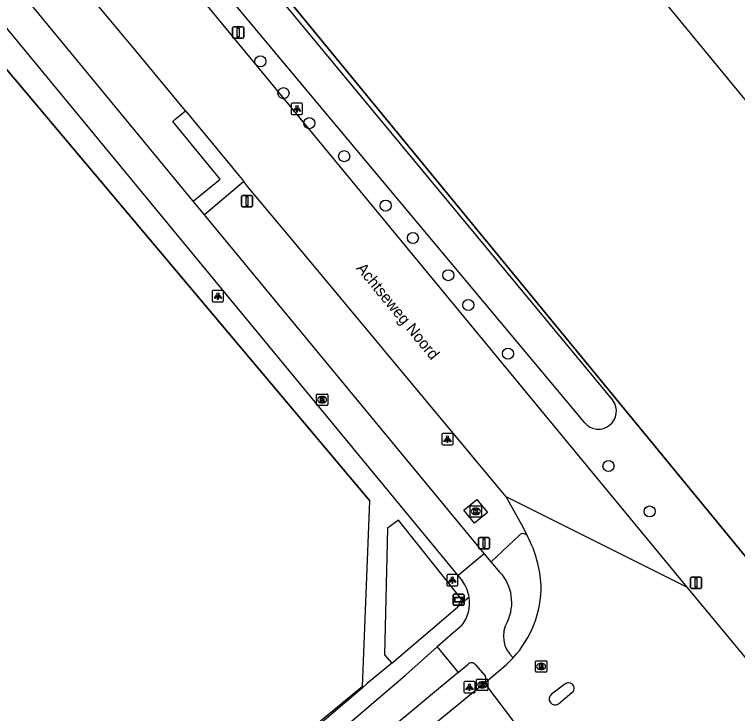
# Model space of a CAD drawing. Extents: x 156141 to 158132, y 385651 to 388399.
# Drawn here: x 157411.4 to 157475.3, y 386650.1 to 386711.9 of the extents above; entities that cross this region are included whole.
import ezdxf

# ---------------------------------------------------------------- set-up
doc = ezdxf.new("R2010")
doc.units = 0
for name, color, linetype in [('IMGEO_Berm_groen', 7, 'Continuous'), ('IMGEO_Berm_open', 7, 'Continuous'), ('IMGEO_Boom', 7, 'Continuous'), ('IMGEO_Fietspad_gesloten', 7, 'Continuous'), ('IMGEO_Fietspad_open', 7, 'Continuous'), ('IMGEO_Groenvoorziening', 7, 'Continuous'), ('IMGEO_Hek', 7, 'Continuous'), ('IMGEO_Kolk', 7, 'Continuous'), ('IMGEO_Lichtpunt', 7, 'Continuous'), ('IMGEO_Openbare_ruimte_label', 7, 'Continuous'), ('IMGEO_Rijbaan_lokaal_gesloten', 7, 'Continuous'), ('IMGEO_Rijbaan_lokaal_open', 7, 'Continuous'), ('IMGEO_Rioolput', 7, 'Continuous'), ('IMGEO_Verkeersbordpaal', 7, 'Continuous'), ('IMGEO_Verklikker', 7, 'Continuous'), ('IMGEO_Voetpad_open', 7, 'Continuous'), ('IMGEO_Waterloop', 7, 'Continuous')]:
    doc.layers.add(name, color=color, linetype=linetype)

msp = doc.modelspace()

# ---------------------------------------------------------------- linework, layer by layer
at = {"layer": 'IMGEO_Berm_groen'}
for points in [[(157442.134, 386652.366), (157442.138, 386652.478), (157442.779, 386668.903), (157366.554, 386759.475), (157367.449, 386760.214), (157328.468, 386807.48), (157305.149, 386835.748), (157305.371, 386835.926), (157306.254, 386836.693)], [(157453.195, 386667.87), (157452.049, 386666.904), (157451.094, 386668.062), (157452.249, 386668.999), (157453.195, 386667.87)], [(157450.547, 386659.488), (157450.88, 386660.201), (157445.328, 386667.193), (157444.342, 386666.47), (157444.073, 386655.269), (157444.717, 386654.548)]]:
    msp.add_lwpolyline(points, dxfattribs=at)
at = {"layer": 'IMGEO_Berm_open'}
msp.add_lwpolyline([(157456.011, 386665.871), (157453.509, 386663.504)], dxfattribs=at)
msp.add_arc((157456.324, 386665.519), 0.471, 25.37119, 131.65084, dxfattribs=at)
at = {"layer": 'IMGEO_Boom'}
for centre in [(157433.117, 386707.739), (157435.158, 386704.93), (157437.436, 386702.279), (157440.518, 386699.359), (157444.183, 386694.993), (157446.592, 386692.131), (157449.727, 386688.836), (157451.485, 386686.203), (157454.999, 386681.904), (157463.879, 386671.978), (157467.514, 386667.952)]:
    msp.add_circle(centre, 0.489, dxfattribs=at)
at = {"layer": 'IMGEO_Fietspad_gesloten'}
for points in [[(157306.254, 386836.693), (157307.173, 386835.584), (157317.744, 386823.128), (157324.427, 386815.039), (157329.795, 386808.571), (157345.284, 386789.91), (157378.223, 386750), (157413.308, 386707.49), (157450.572, 386662.298)], [(157427.18, 386695.379), (157410.042, 386716.143)], [(157428.171, 386694.179), (157427.18, 386695.379)], [(157452.881, 386664.24), (157428.171, 386694.179)], [(157450.572, 386662.298), (157452.881, 386664.24)], [(157388.924, 386606.194), (157432.202, 386641.872), (157439.098, 386647.651), (157445.938, 386653.466), (157448.75, 386655.977)], [(157448.75, 386655.977), (157450.605, 386653.724)], [(157450.605, 386653.724), (157437.983, 386643.221), (157390.577, 386604.195)]]:
    msp.add_lwpolyline(points, dxfattribs=at)
at = {"layer": 'IMGEO_Fietspad_open'}
for points in [[(157453.509, 386663.504), (157452.881, 386664.24)], [(157454.305, 386662.57), (157453.509, 386663.504)], [(157450.572, 386662.298), (157450.979, 386661.776)], [(157450.909, 386657.873), (157450.08, 386657.165), (157448.75, 386655.977)], [(157450.605, 386653.724), (157451.438, 386654.417)], [(157452.12, 386654.393), (157452.973, 386653.414)]]:
    msp.add_lwpolyline(points, dxfattribs=at)
for centre, radius, start, end in [((157451.386, 386659.914), 3.946, 334.70293, 42.29924), ((157448.401, 386659.871), 3.206, 8.88283, 36.46074), ((157448.398, 386659.87), 3.209, 321.49988, 8.88633), ((157457.115, 386656.932), 2.52, 149.05739, 229.14689), ((157451.77, 386654.14), 0.432, 35.79806, 140.17105), ((157452.519, 386653.134), 0.534, 319.38165, 31.69536)]:
    msp.add_arc(centre, radius, start, end, dxfattribs=at)
at = {"layer": 'IMGEO_Groenvoorziening'}
msp.add_lwpolyline([(157429.239, 386720.934), (157498.496, 386636.57), (157500, 386634.738), (157500.222, 386634.47), (157521.784, 386608.449), (157576.014, 386543.004), (157577.215, 386541.551)], dxfattribs=at)
at = {"layer": 'IMGEO_Hek'}
for points in [[(157367.449, 386760.214), (157366.554, 386759.475), (157442.779, 386668.903)], [(157498.496, 386636.57), (157429.239, 386720.934)], [(157442.138, 386652.478), (157442.779, 386668.903)], [(157442.138, 386652.478), (157400.211, 386617.877), (157400.156, 386617.832)], [(157442.134, 386652.366), (157442.138, 386652.478)]]:
    msp.add_lwpolyline(points, dxfattribs=at)
at = {"layer": 'IMGEO_Kolk'}
for p, q in [((157451.655, 386667.535), (157451.655, 386668.387)), ((157451.73, 386668.461), (157452.582, 386668.461)), ((157452.143, 386668.241), (157452.168, 386668.241)), ((157452.656, 386668.387), (157452.656, 386667.535)), ((157452.582, 386667.461), (157451.73, 386667.461)), ((157452.166, 386667.681), (157452.141, 386667.681)), ((157452.225, 386652.206), (157452.225, 386653.058)), ((157452.3, 386653.132), (157453.152, 386653.132)), ((157452.713, 386652.912), (157452.738, 386652.912)), ((157453.226, 386653.058), (157453.226, 386652.206)), ((157453.152, 386652.132), (157452.3, 386652.132)), ((157452.736, 386652.352), (157452.711, 386652.352))]:
    msp.add_line(p, q, dxfattribs=at)
for points in [[(157451.655, 386667.535), (157451.655, 386668.387)], [(157451.73, 386668.461), (157452.582, 386668.461)], [(157451.976, 386668.161), (157452.099, 386668.161), (157452.099, 386668.01), (157452.229, 386668.161), (157452.393, 386668.161), (157452.247, 386668.01), (157452.4, 386667.761), (157452.248, 386667.761), (157452.163, 386667.925), (157452.099, 386667.858), (157452.099, 386667.761), (157451.976, 386667.761), (157451.976, 386668.161)], [(157452.656, 386668.387), (157452.656, 386667.535)], [(157452.582, 386667.461), (157451.73, 386667.461)], [(157452.225, 386652.206), (157452.225, 386653.058)], [(157452.3, 386653.132), (157453.152, 386653.132)], [(157452.546, 386652.832), (157452.669, 386652.832), (157452.669, 386652.681), (157452.799, 386652.832), (157452.963, 386652.832), (157452.817, 386652.681), (157452.97, 386652.432), (157452.818, 386652.432), (157452.733, 386652.596), (157452.669, 386652.529), (157452.669, 386652.432), (157452.546, 386652.432), (157452.546, 386652.832)], [(157453.226, 386653.058), (157453.226, 386652.206)], [(157453.152, 386652.132), (157452.3, 386652.132)]]:
    msp.add_lwpolyline(points, dxfattribs=at)
for centre, start, end in [((157451.732, 386668.385), 91.55205, 178.44795), ((157451.732, 386668.385), 91.55205, 178.44795), ((157452.58, 386668.385), 1.55205, 88.44795), ((157452.58, 386668.385), 1.55205, 88.44795), ((157451.732, 386667.537), 181.55205, 268.44795), ((157451.732, 386667.537), 181.55205, 268.44795), ((157452.58, 386667.537), 271.55205, 358.44795), ((157452.58, 386667.537), 271.55205, 358.44795), ((157452.302, 386653.056), 91.55205, 178.44795), ((157452.302, 386653.056), 91.55205, 178.44795), ((157453.15, 386653.056), 1.55205, 88.44795), ((157453.15, 386653.056), 1.55205, 88.44795), ((157452.302, 386652.208), 181.55205, 268.44795), ((157452.302, 386652.208), 181.55205, 268.44795), ((157453.15, 386652.208), 271.55205, 358.44795), ((157453.15, 386652.208), 271.55205, 358.44795)]:
    msp.add_arc(centre, 0.0765, start, end, dxfattribs=at)
for centre, major_axis, ratio, start_param, end_param in [((157452.142, 386667.961), (-0.387, 0.002), 0.722429, 4.712389, 7.853982), ((157452.167, 386667.961), (-0.39, 0.002), 0.717154, 1.570796, 4.712389), ((157452.712, 386652.632), (-0.387, 0.002), 0.722429, 4.712389, 7.853982), ((157452.737, 386652.632), (-0.39, 0.002), 0.717154, 1.570796, 4.712389)]:
    msp.add_ellipse(centre, major_axis=major_axis, ratio=ratio, start_param=start_param, end_param=end_param, dxfattribs=at)
at = {"layer": 'IMGEO_Lichtpunt'}
for p, q in [((157435.846, 386703.949), (157435.846, 386703.142)), ((157435.846, 386703.949), (157435.846, 386703.142)), ((157436.748, 386704.044), (157435.94, 386704.044)), ((157436.748, 386704.044), (157435.94, 386704.044)), ((157436.842, 386703.142), (157436.842, 386703.949)), ((157436.842, 386703.142), (157436.842, 386703.949)), ((157435.94, 386703.048), (157436.748, 386703.048)), ((157435.94, 386703.048), (157436.748, 386703.048)), ((157428.86, 386687.396), (157428.86, 386686.589)), ((157428.86, 386687.396), (157428.86, 386686.589)), ((157429.762, 386687.491), (157428.954, 386687.491)), ((157429.762, 386687.491), (157428.954, 386687.491)), ((157429.856, 386686.589), (157429.856, 386687.396)), ((157429.856, 386686.589), (157429.856, 386687.396)), ((157428.954, 386686.495), (157429.762, 386686.495)), ((157428.954, 386686.495), (157429.762, 386686.495)), ((157449.149, 386674.745), (157449.149, 386673.938)), ((157449.149, 386674.745), (157449.149, 386673.938)), ((157450.051, 386674.84), (157449.243, 386674.84)), ((157450.051, 386674.84), (157449.243, 386674.84)), ((157450.145, 386673.938), (157450.145, 386674.745)), ((157450.145, 386673.938), (157450.145, 386674.745)), ((157449.243, 386673.844), (157450.051, 386673.844)), ((157449.243, 386673.844), (157450.051, 386673.844)), ((157449.58, 386662.29), (157449.58, 386661.483)), ((157449.58, 386662.29), (157449.58, 386661.483)), ((157450.482, 386662.385), (157449.674, 386662.385)), ((157450.482, 386662.385), (157449.674, 386662.385)), ((157450.576, 386661.483), (157450.576, 386662.29)), ((157450.576, 386661.483), (157450.576, 386662.29)), ((157449.674, 386661.389), (157450.482, 386661.389)), ((157449.674, 386661.389), (157450.482, 386661.389)), ((157451.095, 386652.822), (157451.095, 386652.015)), ((157451.095, 386652.822), (157451.095, 386652.015)), ((157451.997, 386652.917), (157451.189, 386652.917)), ((157451.997, 386652.917), (157451.189, 386652.917)), ((157452.091, 386652.015), (157452.091, 386652.822)), ((157452.091, 386652.015), (157452.091, 386652.822)), ((157451.189, 386651.921), (157451.997, 386651.921)), ((157451.189, 386651.921), (157451.997, 386651.921))]:
    msp.add_line(p, q, dxfattribs=at)
for points in [[(157436.22, 386703.613), (157436.259, 386703.585), (157436.071, 386703.323), (157436.033, 386703.35), (157436.22, 386703.613)], [(157436.322, 386703.565), (157436.369, 386703.565), (157436.369, 386703.243), (157436.322, 386703.243), (157436.322, 386703.565)], [(157436.432, 386703.585), (157436.47, 386703.612), (157436.657, 386703.35), (157436.618, 386703.322), (157436.432, 386703.585)], [(157429.234, 386687.06), (157429.273, 386687.032), (157429.085, 386686.77), (157429.047, 386686.797), (157429.234, 386687.06)], [(157429.336, 386687.012), (157429.383, 386687.012), (157429.383, 386686.69), (157429.336, 386686.69), (157429.336, 386687.012)], [(157429.446, 386687.032), (157429.484, 386687.059), (157429.671, 386686.797), (157429.632, 386686.769), (157429.446, 386687.032)], [(157449.523, 386674.409), (157449.562, 386674.381), (157449.374, 386674.119), (157449.336, 386674.146), (157449.523, 386674.409)], [(157449.625, 386674.361), (157449.672, 386674.361), (157449.672, 386674.039), (157449.625, 386674.039), (157449.625, 386674.361)], [(157449.735, 386674.381), (157449.773, 386674.408), (157449.96, 386674.146), (157449.921, 386674.118), (157449.735, 386674.381)], [(157449.954, 386661.954), (157449.993, 386661.926), (157449.805, 386661.664), (157449.767, 386661.691), (157449.954, 386661.954)], [(157450.056, 386661.906), (157450.103, 386661.906), (157450.103, 386661.584), (157450.056, 386661.584), (157450.056, 386661.906)], [(157450.166, 386661.926), (157450.204, 386661.953), (157450.391, 386661.691), (157450.352, 386661.663), (157450.166, 386661.926)], [(157451.469, 386652.486), (157451.508, 386652.458), (157451.32, 386652.196), (157451.282, 386652.223), (157451.469, 386652.486)], [(157451.571, 386652.438), (157451.618, 386652.438), (157451.618, 386652.116), (157451.571, 386652.116), (157451.571, 386652.438)], [(157451.681, 386652.458), (157451.719, 386652.485), (157451.906, 386652.223), (157451.867, 386652.195), (157451.681, 386652.458)]]:
    msp.add_lwpolyline(points, dxfattribs=at)
for centre in [(157436.345, 386703.747), (157429.359, 386687.194), (157449.648, 386674.543), (157450.079, 386662.088), (157451.594, 386652.62)]:
    msp.add_circle(centre, 0.0994, dxfattribs=at)
for centre, start, end in [((157435.94, 386703.949), 90, 180), ((157435.94, 386703.949), 90, 180), ((157436.748, 386703.949), 0, 90), ((157436.748, 386703.949), 0, 90), ((157435.94, 386703.142), 180, 270), ((157435.94, 386703.142), 180, 270), ((157436.748, 386703.142), 270, 0), ((157436.748, 386703.142), 270, 360), ((157428.954, 386687.396), 90, 180), ((157428.954, 386687.396), 90, 180), ((157429.762, 386687.396), 0, 90), ((157429.762, 386687.396), 0, 90), ((157428.954, 386686.589), 180, 270), ((157428.954, 386686.589), 180, 270), ((157429.762, 386686.589), 270, 0), ((157429.762, 386686.589), 270, 360), ((157449.243, 386674.745), 90, 180), ((157449.243, 386674.745), 90, 180), ((157450.051, 386674.745), 0, 90), ((157450.051, 386674.745), 0, 90), ((157449.243, 386673.938), 180, 270), ((157449.243, 386673.938), 180, 270), ((157450.051, 386673.938), 270, 0), ((157450.051, 386673.938), 270, 360), ((157449.674, 386662.29), 90, 180), ((157449.674, 386662.29), 90, 180), ((157450.482, 386662.29), 0, 90), ((157450.482, 386662.29), 0, 90), ((157449.674, 386661.483), 180, 270), ((157449.674, 386661.483), 180, 270), ((157450.482, 386661.483), 270, 0), ((157450.482, 386661.483), 270, 360), ((157451.189, 386652.822), 90, 180), ((157451.189, 386652.822), 90, 180), ((157451.997, 386652.822), 0, 90), ((157451.997, 386652.822), 0, 90), ((157451.189, 386652.015), 180, 270), ((157451.189, 386652.015), 180, 270), ((157451.997, 386652.015), 270, 0), ((157451.997, 386652.015), 270, 360)]:
    msp.add_arc(centre, 0.0946, start, end, dxfattribs=at)
at = {"layer": 'IMGEO_Rijbaan_lokaal_gesloten'}
for points in [[(157426.489, 386703.354), (157422.539, 386708.146), (157422.419, 386708.292), (157417.313, 386714.46), (157412.339, 386720.535)], [(157428.271, 386712.826), (157470.805, 386661.255)], [(157426.489, 386703.354), (157431.636, 386697.108)], [(157454.834, 386669.244), (157436.573, 386691.201), (157432.018, 386696.645), (157431.636, 386697.108)], [(157456.749, 386665.721), (157456.378, 386666.515), (157454.834, 386669.244)], [(157470.805, 386661.255), (157454.834, 386669.244)], [(157470.805, 386661.255), (157479.667, 386650.565), (157483.034, 386646.48)], [(157452.924, 386652.786), (157454.876, 386654.437), (157455.467, 386655.026)], [(157452.924, 386652.786), (157429.506, 386633.553), (157391.761, 386602.481)], [(157452.924, 386652.786), (157455.672, 386649.151)], [(157460.034, 386652.674), (157458.834, 386651.795)], [(157459.472, 386650.948), (157460.653, 386651.949)]]:
    msp.add_lwpolyline(points, dxfattribs=at)
for centre, radius, start, end in [((157447.137, 386660.783), 10.806, 3.39821, 27.18873), ((157448.567, 386661.347), 9.358, 317.5105, 0.4733), ((157460.361, 386652.327), 0.477, 307.66798, 133.31296), ((157459.163, 386651.379), 0.53, 128.31144, 305.6661)]:
    msp.add_arc(centre, radius, start, end, dxfattribs=at)
at = {"layer": 'IMGEO_Rijbaan_lokaal_open'}
msp.add_lwpolyline([(157450.558, 386733.435), (157457.392, 386725.092), (157458.988, 386724.974), (157499.285, 386675.982), (157504.842, 386672.218), (157506.562, 386670.927), (157507.494, 386669.816), (157537.512, 386633.609), (157538.587, 386631.817), (157541.431, 386623.01), (157541.945, 386621.409), (157542.471, 386620.501), (157543.438, 386619.234), (157590.926, 386561.841), (157589.85, 386560.921), (157592.694, 386557.455), (157588.118, 386553.679), (157591.535, 386549.497), (157579.081, 386539.302)], dxfattribs=at)
at = {"layer": 'IMGEO_Rioolput'}
for p, q in [((157438.068, 386677.408), (157438.068, 386678.26)), ((157438.143, 386678.334), (157438.995, 386678.334)), ((157439.069, 386678.26), (157439.069, 386677.408)), ((157438.556, 386678.114), (157438.581, 386678.114)), ((157438.995, 386677.334), (157438.143, 386677.334)), ((157438.579, 386677.554), (157438.554, 386677.554)), ((157457.424, 386653.823), (157457.424, 386654.675)), ((157457.499, 386654.749), (157458.351, 386654.749)), ((157458.425, 386654.675), (157458.425, 386653.823)), ((157457.912, 386654.529), (157457.937, 386654.529)), ((157458.351, 386653.749), (157457.499, 386653.749)), ((157457.935, 386653.969), (157457.91, 386653.969))]:
    msp.add_line(p, q, dxfattribs=at)
for points in [[(157438.068, 386677.408), (157438.068, 386678.26)], [(157438.143, 386678.334), (157438.995, 386678.334)], [(157439.069, 386678.26), (157439.069, 386677.408)], [(157438.657, 386678.032), (157438.405, 386678.034), (157438.405, 386677.634)], [(157438.405, 386677.634), (157438.529, 386677.634), (157438.529, 386677.796), (157438.54, 386677.796)], [(157438.583, 386677.953), (157438.529, 386677.953), (157438.529, 386677.872)], [(157438.529, 386677.872), (157438.581, 386677.872)], [(157438.587, 386677.767), (157438.658, 386677.634), (157438.798, 386677.634), (157438.733, 386677.76)], [(157438.995, 386677.334), (157438.143, 386677.334)], [(157457.424, 386653.823), (157457.424, 386654.675)], [(157457.499, 386654.749), (157458.351, 386654.749)], [(157458.425, 386654.675), (157458.425, 386653.823)], [(157458.013, 386654.447), (157457.761, 386654.449), (157457.761, 386654.049)], [(157457.761, 386654.049), (157457.885, 386654.049), (157457.885, 386654.211), (157457.896, 386654.211)], [(157457.939, 386654.368), (157457.885, 386654.368), (157457.885, 386654.287)], [(157457.885, 386654.287), (157457.937, 386654.287)], [(157457.943, 386654.182), (157458.014, 386654.049), (157458.154, 386654.049), (157458.089, 386654.175)], [(157458.351, 386653.749), (157457.499, 386653.749)]]:
    msp.add_lwpolyline(points, dxfattribs=at)
for centre, radius, start, end in [((157438.145, 386678.258), 0.0765, 91.55205, 178.44795), ((157438.145, 386678.258), 0.0765, 91.55205, 178.44795), ((157438.993, 386678.258), 0.0765, 1.55205, 88.44795), ((157438.993, 386678.258), 0.0765, 1.55205, 88.44795), ((157438.539, 386677.743), 0.0533, 26.02933, 88.69889), ((157438.565, 386678.061), 0.19, 274.7715, 282.96867), ((157438.589, 386677.857), 0.0964, 77.00612, 93.18647), ((157438.603, 386677.914), 0.0378, 276.66336, 79.67722), ((157438.656, 386677.922), 0.109, 350.36119, 89.41601), ((157438.654, 386677.922), 0.112, 277.58423, 350.98172), ((157438.638, 386677.707), 0.108, 29.51342, 73.79051), ((157438.145, 386677.41), 0.0765, 181.55205, 268.44795), ((157438.145, 386677.41), 0.0765, 181.55205, 268.44795), ((157438.993, 386677.41), 0.0765, 271.55205, 358.44795), ((157438.993, 386677.41), 0.0765, 271.55205, 358.44795), ((157457.501, 386654.673), 0.0765, 91.55205, 178.44795), ((157457.501, 386654.673), 0.0765, 91.55205, 178.44795), ((157458.349, 386654.673), 0.0765, 1.55205, 88.44795), ((157458.349, 386654.673), 0.0765, 1.55205, 88.44795), ((157457.895, 386654.158), 0.0533, 26.02933, 88.69889), ((157457.921, 386654.476), 0.19, 274.7715, 282.96867), ((157457.945, 386654.272), 0.0964, 77.00612, 93.18647), ((157457.959, 386654.329), 0.0378, 276.66336, 79.67722), ((157458.012, 386654.337), 0.109, 350.36119, 89.41601), ((157458.01, 386654.337), 0.112, 277.58423, 350.98172), ((157457.994, 386654.122), 0.108, 29.51342, 73.79051), ((157457.501, 386653.825), 0.0765, 181.55205, 268.44795), ((157457.501, 386653.825), 0.0765, 181.55205, 268.44795), ((157458.349, 386653.825), 0.0765, 271.55205, 358.44795), ((157458.349, 386653.825), 0.0765, 271.55205, 358.44795)]:
    msp.add_arc(centre, radius, start, end, dxfattribs=at)
for centre, major_axis, ratio, start_param, end_param in [((157438.555, 386677.834), (-0.387, 0.002), 0.722429, 4.712389, 7.853982), ((157438.58, 386677.834), (-0.39, 0.002), 0.717154, 1.570796, 4.712389), ((157457.911, 386654.249), (-0.387, 0.002), 0.722429, 4.712389, 7.853982), ((157457.936, 386654.249), (-0.39, 0.002), 0.717154, 1.570796, 4.712389)]:
    msp.add_ellipse(centre, major_axis=major_axis, ratio=ratio, start_param=start_param, end_param=end_param, dxfattribs=at)
at = {"layer": 'IMGEO_Verkeersbordpaal'}
for p, q in [((157430.655, 386709.898), (157430.655, 386710.698)), ((157430.655, 386710.698), (157430.655, 386709.898)), ((157430.755, 386710.798), (157431.545, 386710.798)), ((157431.545, 386710.798), (157430.755, 386710.798)), ((157431.645, 386710.698), (157431.645, 386709.898)), ((157431.645, 386709.898), (157431.645, 386710.698)), ((157431.545, 386709.798), (157430.755, 386709.798)), ((157430.755, 386709.798), (157431.545, 386709.798)), ((157431.439, 386694.987), (157431.439, 386695.787)), ((157431.439, 386695.787), (157431.439, 386694.987)), ((157431.539, 386695.887), (157432.329, 386695.887)), ((157432.329, 386695.887), (157431.539, 386695.887)), ((157432.429, 386695.787), (157432.429, 386694.987)), ((157432.429, 386694.987), (157432.429, 386695.787)), ((157432.329, 386694.887), (157431.539, 386694.887)), ((157431.539, 386694.887), (157432.329, 386694.887)), ((157452.38, 386664.752), (157452.38, 386665.552)), ((157452.38, 386665.552), (157452.38, 386664.752)), ((157452.48, 386665.652), (157453.27, 386665.652)), ((157453.27, 386665.652), (157452.48, 386665.652)), ((157453.37, 386665.552), (157453.37, 386664.752)), ((157453.37, 386664.752), (157453.37, 386665.552)), ((157453.27, 386664.652), (157452.48, 386664.652)), ((157452.48, 386664.652), (157453.27, 386664.652)), ((157471.122, 386661.243), (157471.122, 386662.043)), ((157471.122, 386662.043), (157471.122, 386661.243)), ((157471.222, 386662.143), (157472.012, 386662.143)), ((157472.012, 386662.143), (157471.222, 386662.143)), ((157472.112, 386662.043), (157472.112, 386661.243)), ((157472.112, 386661.243), (157472.112, 386662.043)), ((157472.012, 386661.143), (157471.222, 386661.143)), ((157471.222, 386661.143), (157472.012, 386661.143))]:
    msp.add_line(p, q, dxfattribs=at)
for points in [[(157431.075, 386710.673), (157431.225, 386710.673), (157431.225, 386709.923), (157431.075, 386709.923), (157431.075, 386710.673)], [(157431.859, 386695.762), (157432.009, 386695.762), (157432.009, 386695.012), (157431.859, 386695.012), (157431.859, 386695.762)], [(157452.8, 386665.527), (157452.95, 386665.527), (157452.95, 386664.777), (157452.8, 386664.777), (157452.8, 386665.527)], [(157471.542, 386662.018), (157471.692, 386662.018), (157471.692, 386661.268), (157471.542, 386661.268), (157471.542, 386662.018)]]:
    msp.add_lwpolyline(points, dxfattribs=at)
for centre, start, end in [((157430.755, 386710.698), 90, 180), ((157430.755, 386710.698), 90, 180), ((157431.545, 386710.698), 0, 90), ((157431.545, 386710.698), 360, 90), ((157430.755, 386709.898), 180, 270), ((157430.755, 386709.898), 180, 270), ((157431.545, 386709.898), 270, 0), ((157431.545, 386709.898), 270, 0), ((157431.539, 386695.787), 90, 180), ((157431.539, 386695.787), 90, 180), ((157432.329, 386695.787), 0, 90), ((157432.329, 386695.787), 360, 90), ((157431.539, 386694.987), 180, 270), ((157431.539, 386694.987), 180, 270), ((157432.329, 386694.987), 270, 0), ((157432.329, 386694.987), 270, 0), ((157452.48, 386665.552), 90, 180), ((157452.48, 386665.552), 90, 180), ((157453.27, 386665.552), 0, 90), ((157453.27, 386665.552), 360, 90), ((157452.48, 386664.752), 180, 270), ((157452.48, 386664.752), 180, 270), ((157453.27, 386664.752), 270, 0), ((157453.27, 386664.752), 270, 0), ((157471.222, 386662.043), 90, 180), ((157471.222, 386662.043), 90, 180), ((157472.012, 386662.043), 0, 90), ((157472.012, 386662.043), 360, 90), ((157471.222, 386661.243), 180, 270), ((157471.222, 386661.243), 180, 270), ((157472.012, 386661.243), 270, 0), ((157472.012, 386661.243), 270, 0)]:
    msp.add_arc(centre, 0.1, start, end, dxfattribs=at)
at = {"layer": 'IMGEO_Verklikker'}
for p, q in [((157450.14, 386659.754), (157450.14, 386660.554)), ((157450.14, 386660.554), (157450.14, 386659.754)), ((157450.24, 386660.654), (157451.03, 386660.654)), ((157451.03, 386660.654), (157450.24, 386660.654)), ((157451.13, 386660.554), (157451.13, 386659.754)), ((157451.13, 386659.754), (157451.13, 386660.554)), ((157451.03, 386659.654), (157450.24, 386659.654)), ((157450.24, 386659.654), (157451.03, 386659.654))]:
    msp.add_line(p, q, dxfattribs=at)
for points in [[(157450.241, 386660.386), (157451.029, 386660.386), (157451.029, 386659.922), (157450.241, 386659.922), (157450.241, 386660.386)], [(157450.306, 386660.321), (157450.306, 386659.987), (157450.964, 386659.987), (157450.964, 386660.321), (157450.306, 386660.321)]]:
    msp.add_lwpolyline(points, dxfattribs=at)
for centre, start, end in [((157450.24, 386660.554), 90, 180), ((157450.24, 386660.554), 90, 180), ((157451.03, 386660.554), 0, 90), ((157451.03, 386660.554), 360, 90), ((157450.24, 386659.754), 180, 270), ((157450.24, 386659.754), 180, 270), ((157451.03, 386659.754), 270, 0), ((157451.03, 386659.754), 270, 0)]:
    msp.add_arc(centre, 0.1, start, end, dxfattribs=at)
at = {"layer": 'IMGEO_Voetpad_open'}
for points in [[(157427.18, 386695.379), (157429.571, 386697.329), (157425.362, 386702.432), (157425.553, 386702.588), (157426.489, 386703.354)], [(157431.636, 386697.108), (157428.171, 386694.179)], [(157451.568, 386660.366), (157450.547, 386659.488)], [(157444.717, 386654.548), (157449.13, 386658.27), (157450.547, 386659.488)], [(157444.717, 386654.548), (157442.563, 386652.731), (157442.134, 386652.366)], [(157442.134, 386652.366), (157438.365, 386649.162), (157433.089, 386644.724), (157395.427, 386613.635)]]:
    msp.add_lwpolyline(points, dxfattribs=at)
at = {"layer": 'IMGEO_Waterloop'}
for points in [[(157431.788, 386716.982), (157464.266, 386677.772)], [(157461.774, 386675.786), (157429.02, 386714.993)]]:
    msp.add_lwpolyline(points, dxfattribs=at)
msp.add_arc((157462.981, 386676.828), 1.595, 220.79748, 36.30873, dxfattribs=at)

# ---------------------------------------------------------------- texts
at = {"layer": 'IMGEO_Openbare_ruimte_label'}
msp.add_text('Achtseweg Noord', height=1, rotation=309.43862, dxfattribs=at).set_placement((157441.537, 386689.422))

doc.saveas('drawing.dxf')
